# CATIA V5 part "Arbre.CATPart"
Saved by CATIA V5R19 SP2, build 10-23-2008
Part number: Arbre
Bounding box of the stored display mesh (mm): x -20 to 20, y -656 to -646, z 470 to 480
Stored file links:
  G:\EU_thinkMotion\CFAO_2010\MMS_groupe3\MMS_groupe3\pmayet\pmayet_assemblage_animation\pmayet_assemblage_animation\Arbre.CATPart
  G:\EU_thinkMotion\CFAO_2010\MMS_groupe3\MMS_groupe3\pmayet\pmayet_assemblage_animation\pmayet_assemblage_animation\pmayet_assemblage_animation.CATProduct
  G:\EU_thinkMotion\CFAO_2010\MMS_groupe3\MMS_groupe3\pmayet\pmayet_assemblage_animation\pmayet_assemblage_animation\Squelette_amortisseur.CATPart
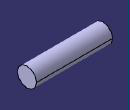
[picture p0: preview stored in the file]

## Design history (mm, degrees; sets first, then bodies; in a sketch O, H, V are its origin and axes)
Parameters
  Rayon_trou_amortisseur = 5 mm
  Longueur_arbre = 20 mm
Set1
  Plane1: linked copy from another document
  Point1 "Point.20_amortisseur": linked copy from another document
Body1 (main body)
  Sketch1 on Plane1, origin (0, 0, 0), H (0, 1, 0), V (0, 0, 1)
    circle A1 centre (-651, 475) radius 5
    point P1 (-651, 475)
    reference projected point E1 (-651, 475) from Point1
    distance P1 A1 = 5 {= Rayon_trou_amortisseur}
    coincidence: P1 E1
  Pad1: profile Sketch1, direction (1, 0, 0), length 20 {= Longueur_arbre}, mirrored extent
